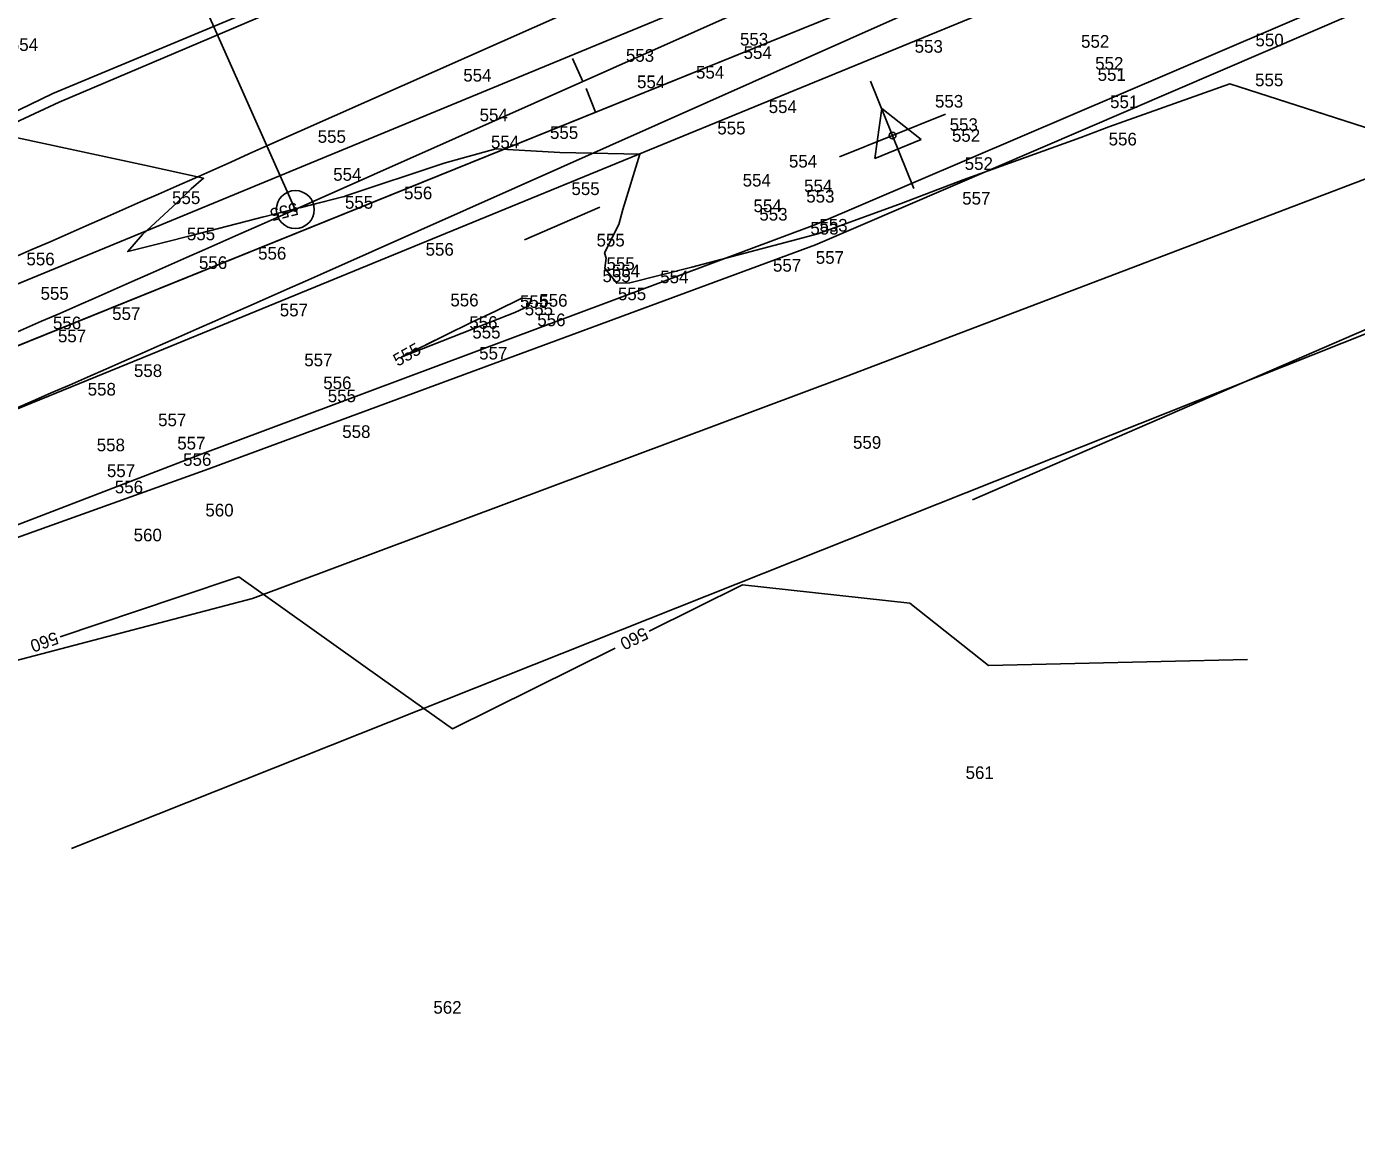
# Model space of a CAD drawing. Extents: x 1787461 to 1970323, y 938412 to 1118748.
# Drawn here: x 1966957.7 to 1967168, y 1117405.8 to 1117583.4 of the extents above; entities that cross this region are included whole.
import ezdxf

# ---------------------------------------------------------------- set-up
doc = ezdxf.new("R2010")
doc.units = 0
for name, color, linetype in [('Default', 7, 'Continuous'), ('HHA ADDITIONAL XSs', 7, 'Continuous'), ('Level 1', 7, 'Continuous'), ('RD_EX_DR_Pipe', 7, 'Continuous'), ('RD_EX_DV_Prop', 7, 'Continuous'), ('RD_EX_Fence_Other', 7, 'Continuous'), ('RD_EX_Road', 7, 'Continuous'), ('RD_EX_VEG', 7, 'Continuous'), ('RD_HC_CL', 7, 'Continuous'), ('RD_HC_CL_Rel', 7, 'Continuous'), ('RD_HC_Data', 7, 'Continuous'), ('RD_HC_Data_Rel', 7, 'Continuous'), ('RD_HC_Data_Tic', 7, 'Continuous'), ('RD_HC_Data_Tic_Rel', 7, 'Continuous'), ('RD_PD_Final_TrvlWay', 7, 'Continuous'), ('RD_SMD_Locator', 7, 'Continuous')]:
    doc.layers.add(name, color=color, linetype=linetype)

msp = doc.modelspace()

# ---------------------------------------------------------------- linework, layer by layer
at = {"layer": 'Default'}
for points in [[(1966956.22, 1117565.78), (1966976.29, 1117561.41), (1966985.65, 1117559.37), (1966983.68, 1117557.71), (1966981.41, 1117555.46), (1966976, 1117550.46), (1966973.66, 1117547.76), (1966979.57, 1117549.27), (1966983.55, 1117550.28), (1966993.93, 1117552.93), (1967007.69, 1117556.42), (1967007.94, 1117556.5), (1967008.17, 1117556.58), (1967023.71, 1117561.74), (1967031.88, 1117564.04), (1967042.04, 1117563.46), (1967054.65, 1117563.2), (1967051.98, 1117554.44), (1967051.36, 1117552.04), (1967049.1, 1117547.57), (1967049.36, 1117546.73), (1967049.11, 1117545.12), (1967051.03, 1117542.76), (1967053.07, 1117542.82), (1967062.9, 1117545.28), (1967078.65, 1117549.48), (1967082.04, 1117550.36), (1967082.81, 1117550.57), (1967096.02, 1117555.37), (1967105.81, 1117559.1), (1967124.45, 1117565.81), (1967128.88, 1117567.48), (1967148, 1117574.3), (1967186.2, 1117562)], [(1967000.95, 1117554.71), (1967007.69, 1117556.42), (1967007.94, 1117556.5), (1967008.17, 1117556.58), (1967023.71, 1117561.74), (1967031.88, 1117564.04), (1967042.04, 1117563.46), (1967054.65, 1117563.2), (1967051.98, 1117554.44), (1967051.36, 1117552.04), (1967049.1, 1117547.57), (1967049.36, 1117546.73), (1967049.11, 1117545.12), (1967051.03, 1117542.76), (1967053.07, 1117542.82), (1967062.9, 1117545.28), (1967078.65, 1117549.48), (1967082.04, 1117550.36), (1967082.81, 1117550.57), (1967096.02, 1117555.37), (1967105.81, 1117559.1), (1967124.45, 1117565.81), (1967128.88, 1117567.48), (1967148, 1117574.3), (1967167.54, 1117568.01)], [(1967000.95, 1117554.71), (1967007.69, 1117556.42), (1967007.94, 1117556.5), (1967008.17, 1117556.58), (1967023.71, 1117561.74), (1967031.88, 1117564.04), (1967042.04, 1117563.46), (1967054.65, 1117563.2), (1967051.98, 1117554.44), (1967051.36, 1117552.04), (1967049.1, 1117547.57), (1967049.36, 1117546.73), (1967049.11, 1117545.12), (1967051.03, 1117542.76), (1967053.07, 1117542.82), (1967062.9, 1117545.28), (1967078.65, 1117549.48), (1967082.04, 1117550.36), (1967082.81, 1117550.57), (1967096.02, 1117555.37), (1967105.81, 1117559.1), (1967124.45, 1117565.81), (1967128.88, 1117567.48), (1967148, 1117574.3), (1967167.54, 1117568.01)], [(1967000.95, 1117554.71), (1967007.69, 1117556.42), (1967007.94, 1117556.5), (1967008.17, 1117556.58), (1967023.71, 1117561.74), (1967031.88, 1117564.04), (1967042.04, 1117563.46), (1967054.65, 1117563.2), (1967051.98, 1117554.44), (1967051.36, 1117552.04), (1967049.1, 1117547.57), (1967049.36, 1117546.73), (1967049.11, 1117545.12), (1967051.03, 1117542.76), (1967053.07, 1117542.82), (1967062.9, 1117545.28), (1967078.65, 1117549.48), (1967082.04, 1117550.36), (1967082.81, 1117550.57), (1967096.02, 1117555.37), (1967105.81, 1117559.1), (1967124.45, 1117565.81), (1967128.88, 1117567.48), (1967148, 1117574.3), (1967167.54, 1117568.01)], [(1967000.95, 1117554.71), (1967007.69, 1117556.42), (1967007.94, 1117556.5), (1967008.17, 1117556.58), (1967023.71, 1117561.74), (1967031.88, 1117564.04), (1967042.04, 1117563.46), (1967054.65, 1117563.2), (1967051.98, 1117554.44), (1967051.36, 1117552.04), (1967049.1, 1117547.57), (1967049.36, 1117546.73), (1967049.11, 1117545.12), (1967051.03, 1117542.76), (1967053.07, 1117542.82), (1967062.9, 1117545.28), (1967078.65, 1117549.48), (1967082.04, 1117550.36), (1967082.81, 1117550.57), (1967096.02, 1117555.37), (1967105.81, 1117559.1), (1967124.45, 1117565.81), (1967128.88, 1117567.48), (1967148, 1117574.3), (1967167.54, 1117568.01)], [(1967000.95, 1117554.71), (1967007.69, 1117556.42), (1967007.94, 1117556.5), (1967008.17, 1117556.58), (1967023.71, 1117561.74), (1967031.88, 1117564.04), (1967042.04, 1117563.46), (1967054.65, 1117563.2), (1967051.98, 1117554.44), (1967051.36, 1117552.04), (1967049.1, 1117547.57), (1967049.36, 1117546.73), (1967049.11, 1117545.12), (1967051.03, 1117542.76), (1967053.07, 1117542.82), (1967062.9, 1117545.28), (1967078.65, 1117549.48), (1967082.04, 1117550.36), (1967082.81, 1117550.57), (1967096.02, 1117555.37), (1967105.81, 1117559.1), (1967124.45, 1117565.81), (1967128.88, 1117567.48), (1967148, 1117574.3), (1967167.54, 1117568.01)], [(1967000.95, 1117554.71), (1967007.69, 1117556.42), (1967007.94, 1117556.5), (1967008.17, 1117556.58), (1967023.71, 1117561.74), (1967031.88, 1117564.04), (1967042.04, 1117563.46), (1967054.65, 1117563.2), (1967051.98, 1117554.44), (1967051.36, 1117552.04), (1967049.1, 1117547.57), (1967049.36, 1117546.73), (1967049.11, 1117545.12), (1967051.03, 1117542.76), (1967053.07, 1117542.82), (1967062.9, 1117545.28), (1967078.65, 1117549.48), (1967082.04, 1117550.36), (1967082.81, 1117550.57), (1967096.02, 1117555.37), (1967105.81, 1117559.1), (1967124.45, 1117565.81), (1967128.88, 1117567.48), (1967148, 1117574.3), (1967167.54, 1117568.01)], [(1966827.07, 1117562.81), (1966852.87, 1117556.35), (1966869.59, 1117558.18), (1966944.3, 1117568.38), (1966948.44, 1117567.48), (1966956.22, 1117565.78), (1966976.29, 1117561.41), (1966985.65, 1117559.37), (1966983.68, 1117557.71), (1966981.41, 1117555.46), (1966976, 1117550.46), (1966973.66, 1117547.76), (1966979.57, 1117549.27), (1966983.55, 1117550.28), (1966993.93, 1117552.93), (1966995.13, 1117553.24)], [(1966827.07, 1117562.81), (1966852.87, 1117556.35), (1966869.59, 1117558.18), (1966944.3, 1117568.38), (1966948.44, 1117567.48), (1966956.22, 1117565.78), (1966976.29, 1117561.41), (1966985.65, 1117559.37), (1966983.68, 1117557.71), (1966981.41, 1117555.46), (1966976, 1117550.46), (1966973.66, 1117547.76), (1966979.57, 1117549.27), (1966983.55, 1117550.28), (1966993.93, 1117552.93), (1966995.13, 1117553.24)], [(1966827.07, 1117562.81), (1966852.87, 1117556.35), (1966869.59, 1117558.18), (1966944.3, 1117568.38), (1966948.44, 1117567.48), (1966956.22, 1117565.78), (1966976.29, 1117561.41), (1966985.65, 1117559.37), (1966983.68, 1117557.71), (1966981.41, 1117555.46), (1966976, 1117550.46), (1966973.66, 1117547.76), (1966979.57, 1117549.27), (1966983.55, 1117550.28), (1966993.93, 1117552.93), (1966995.13, 1117553.24)], [(1966827.07, 1117562.81), (1966852.87, 1117556.35), (1966869.59, 1117558.18), (1966944.3, 1117568.38), (1966948.44, 1117567.48), (1966956.22, 1117565.78), (1966976.29, 1117561.41), (1966985.65, 1117559.37), (1966983.68, 1117557.71), (1966981.41, 1117555.46), (1966976, 1117550.46), (1966973.66, 1117547.76), (1966979.57, 1117549.27), (1966983.55, 1117550.28), (1966993.93, 1117552.93), (1966995.13, 1117553.24)], [(1966827.07, 1117562.81), (1966852.87, 1117556.35), (1966869.59, 1117558.18), (1966944.3, 1117568.38), (1966948.44, 1117567.48), (1966956.22, 1117565.78), (1966976.29, 1117561.41), (1966985.65, 1117559.37), (1966983.68, 1117557.71), (1966981.41, 1117555.46), (1966976, 1117550.46), (1966973.66, 1117547.76), (1966979.57, 1117549.27), (1966983.55, 1117550.28), (1966993.93, 1117552.93), (1966995.13, 1117553.24)], [(1966827.07, 1117562.81), (1966852.87, 1117556.35), (1966869.59, 1117558.18), (1966944.3, 1117568.38), (1966948.44, 1117567.48), (1966956.22, 1117565.78), (1966976.29, 1117561.41), (1966985.65, 1117559.37), (1966983.68, 1117557.71), (1966981.41, 1117555.46), (1966976, 1117550.46), (1966973.66, 1117547.76), (1966979.57, 1117549.27), (1966983.55, 1117550.28), (1966993.93, 1117552.93), (1966995.13, 1117553.24)], [(1967036.01, 1117540.41), (1967037.52, 1117540.3), (1967037.07, 1117539.15), (1967034.87, 1117538.13), (1967028.32, 1117535.55), (1967016.9, 1117531.06), (1967023.9, 1117534.57), (1967028.01, 1117536.54), (1967031.83, 1117538.37), (1967036.01, 1117540.41)], [(1967036.01, 1117540.41), (1967037.52, 1117540.3), (1967037.07, 1117539.15), (1967034.87, 1117538.13), (1967028.32, 1117535.55), (1967018.39, 1117531.65)], [(1967036.01, 1117540.41), (1967037.52, 1117540.3), (1967037.07, 1117539.15), (1967034.87, 1117538.13), (1967028.32, 1117535.55), (1967018.39, 1117531.65)], [(1967036.01, 1117540.41), (1967037.52, 1117540.3), (1967037.07, 1117539.15), (1967034.87, 1117538.13), (1967028.32, 1117535.55), (1967018.39, 1117531.65)], [(1967036.01, 1117540.41), (1967037.52, 1117540.3), (1967037.07, 1117539.15), (1967034.87, 1117538.13), (1967028.32, 1117535.55), (1967018.39, 1117531.65)], [(1967036.01, 1117540.41), (1967037.52, 1117540.3), (1967037.07, 1117539.15), (1967034.87, 1117538.13), (1967028.32, 1117535.55), (1967018.39, 1117531.65)], [(1967036.01, 1117540.41), (1967037.52, 1117540.3), (1967037.07, 1117539.15), (1967034.87, 1117538.13), (1967028.32, 1117535.55), (1967018.39, 1117531.65)], [(1967020.82, 1117533.03), (1967023.9, 1117534.57), (1967028.01, 1117536.54), (1967031.83, 1117538.37), (1967036.01, 1117540.41)], [(1967020.82, 1117533.03), (1967023.9, 1117534.57), (1967028.01, 1117536.54), (1967031.83, 1117538.37), (1967036.01, 1117540.41)], [(1967020.82, 1117533.03), (1967023.9, 1117534.57), (1967028.01, 1117536.54), (1967031.83, 1117538.37), (1967036.01, 1117540.41)], [(1967020.82, 1117533.03), (1967023.9, 1117534.57), (1967028.01, 1117536.54), (1967031.83, 1117538.37), (1967036.01, 1117540.41)], [(1967020.82, 1117533.03), (1967023.9, 1117534.57), (1967028.01, 1117536.54), (1967031.83, 1117538.37), (1967036.01, 1117540.41)], [(1967020.82, 1117533.03), (1967023.9, 1117534.57), (1967028.01, 1117536.54), (1967031.83, 1117538.37), (1967036.01, 1117540.41)], [(1967050.76, 1117485.04), (1967025.02, 1117472.26), (1967013.95, 1117480.14), (1966991.25, 1117496.3), (1966981.5, 1117493.04), (1966962.98, 1117486.85)], [(1967050.76, 1117485.04), (1967025.02, 1117472.26), (1967013.95, 1117480.14), (1966991.25, 1117496.3), (1966981.5, 1117493.04), (1966962.98, 1117486.85)], [(1967050.76, 1117485.04), (1967025.02, 1117472.26), (1967013.95, 1117480.14), (1966991.25, 1117496.3), (1966981.5, 1117493.04), (1966962.98, 1117486.85)], [(1967050.76, 1117485.04), (1967025.02, 1117472.26), (1967013.95, 1117480.14), (1966991.25, 1117496.3), (1966981.5, 1117493.04), (1966962.98, 1117486.85)], [(1967050.76, 1117485.04), (1967025.02, 1117472.26), (1967013.95, 1117480.14), (1966991.25, 1117496.3), (1966981.5, 1117493.04), (1966962.98, 1117486.85)], [(1967050.76, 1117485.04), (1967025.02, 1117472.26), (1967013.95, 1117480.14), (1966991.25, 1117496.3), (1966981.5, 1117493.04), (1966962.98, 1117486.85)], [(1967050.76, 1117485.04), (1967025.02, 1117472.26), (1967013.95, 1117480.14), (1966991.25, 1117496.3), (1966981.5, 1117493.04), (1966962.98, 1117486.85)], [(1967150.81, 1117483.25), (1967109.82, 1117482.32), (1967097.4, 1117492.18), (1967070.91, 1117495.04), (1967056.14, 1117487.71)], [(1967150.81, 1117483.25), (1967109.82, 1117482.32), (1967097.4, 1117492.18), (1967070.91, 1117495.04), (1967056.14, 1117487.71)], [(1967150.81, 1117483.25), (1967109.82, 1117482.32), (1967097.4, 1117492.18), (1967070.91, 1117495.04), (1967056.14, 1117487.71)], [(1967150.81, 1117483.25), (1967109.82, 1117482.32), (1967097.4, 1117492.18), (1967070.91, 1117495.04), (1967056.14, 1117487.71)], [(1967150.81, 1117483.25), (1967109.82, 1117482.32), (1967097.4, 1117492.18), (1967070.91, 1117495.04), (1967056.14, 1117487.71)], [(1967150.81, 1117483.25), (1967109.82, 1117482.32), (1967097.4, 1117492.18), (1967070.91, 1117495.04), (1967056.14, 1117487.71)], [(1967150.81, 1117483.25), (1967109.82, 1117482.32), (1967097.4, 1117492.18), (1967070.91, 1117495.04), (1967056.14, 1117487.71)]]:
    msp.add_lwpolyline(points, dxfattribs=at)
at = {"layer": 'HHA ADDITIONAL XSs'}
msp.add_lwpolyline([(1969308.89, 1117819.66), (1967912.94, 1117853.44), (1967442.55, 1117653.93), (1967107.32, 1117508.48)], dxfattribs=at)
at = {"layer": 'Level 1'}
msp.add_lwpolyline([(1968654.57, 1117840.68), (1968058.24, 1117848.48), (1967686.38, 1117740.3), (1966964.76, 1117453.35)], dxfattribs=at)
at = {"layer": 'RD_EX_DR_Pipe'}
msp.add_line((1967036.42, 1117549.62), (1967048.36, 1117554.77), dxfattribs=at)
at = {"layer": 'RD_EX_DV_Prop'}
msp.add_line((1966769.51, 1117457.48), (1967696.84, 1117832.06), dxfattribs=at)
at = {"layer": 'RD_EX_Fence_Other'}
for points in [[(1966803.22, 1117549.06), (1966808.8, 1117506.9), (1966864.07, 1117525.43), (1966962.8, 1117571.4), (1967060.23, 1117612.78), (1967157.77, 1117654.58), (1967254.5, 1117693.48), (1967317.6, 1117718.63)], [(1966879.09, 1117474.94), (1966985.88, 1117513.17), (1967082.44, 1117548.84), (1967188.89, 1117594.6), (1967260.47, 1117628.39)], [(1966814.04, 1117405.76), (1966802.15, 1117419.77), (1966805.19, 1117443.48), (1966993.4, 1117492.9), (1967087.17, 1117527.94), (1967198.46, 1117570.29), (1967208.88, 1117573.86), (1967251.36, 1117534.17)]]:
    msp.add_lwpolyline(points, dxfattribs=at)
at = {"layer": 'RD_EX_Road'}
for points in [[(1966768.28, 1117466.83), (1966868.93, 1117506.7), (1966969.96, 1117548.31), (1967069.86, 1117589.6), (1967171.37, 1117630.89), (1967269.56, 1117671.02), (1967319.89, 1117691.93), (1967370.29, 1117712.23), (1967469.03, 1117750.91), (1967565.44, 1117788.86), (1967660.02, 1117826.88), (1967693.17, 1117840.55), (1967696.66, 1117832.16)], [(1966774.52, 1117449.93), (1966874.96, 1117489.75), (1966977.23, 1117531.51), (1967077.03, 1117572.42), (1967179.47, 1117614.42), (1967276.75, 1117654.08), (1967307.6, 1117666.03)]]:
    msp.add_lwpolyline(points, dxfattribs=at)
at = {"layer": 'RD_EX_VEG'}
for points in [[(1966803.22, 1117549.06), (1966801.85, 1117502.56), (1966864.07, 1117525.43), (1966961.82, 1117572.79), (1967059.09, 1117613.38), (1967156.27, 1117655.27), (1967254.08, 1117694.01), (1967316.99, 1117719.5)], [(1966832.92, 1117460.39), (1966879.09, 1117474.94), (1966985, 1117515.6), (1967082.35, 1117552.01), (1967187.28, 1117596.9), (1967283.89, 1117634.57), (1967305.16, 1117647.66)]]:
    msp.add_lwpolyline(points, dxfattribs=at)
at = {"layer": 'RD_HC_CL'}
msp.add_line((1966769.51, 1117457.48), (1967848.24, 1117893.22), dxfattribs=at)
at = {"layer": 'RD_HC_CL_Rel'}
msp.add_line((1967000.16, 1117554.42), (1967182.71, 1117635.7), dxfattribs=at)
msp.add_arc((1964669.71, 1122788.65), 5729.58, 291.995896, 294.000153, dxfattribs=at)
at = {"layer": 'RD_HC_Data'}
for p, q in [((1967098.04, 1117557.74), (1967091.18, 1117574.74)), ((1967086.27, 1117562.73), (1967103.04, 1117569.51)), ((1967091.83, 1117562.51), (1967092.94, 1117570.38)), ((1967092.94, 1117570.38), (1967099.19, 1117565.48)), ((1967091.83, 1117562.51), (1967099.19, 1117565.48))]:
    msp.add_line(p, q, dxfattribs=at)
msp.add_circle((1967094.66, 1117566.12), 0.529, dxfattribs=at)
at = {"layer": 'RD_HC_Data_Rel'}
msp.add_line((1967000.16, 1117554.42), (1966940.2, 1117689.08), dxfattribs=at)
for radius in [3, 0.282]:
    msp.add_circle((1967000.16, 1117554.42), radius, dxfattribs=at)
at = {"layer": 'RD_HC_Data_Tic'}
msp.add_line((1967047.67, 1117569.84), (1967046.18, 1117573.55), dxfattribs=at)
at = {"layer": 'RD_HC_Data_Tic_Rel'}
msp.add_line((1967045.64, 1117574.68), (1967044.02, 1117578.33), dxfattribs=at)
at = {"layer": 'RD_PD_Final_TrvlWay'}
for p, q in [((1966995.68, 1117564.47), (1967178.24, 1117645.75)), ((1967004.63, 1117544.37), (1967187.19, 1117625.65))]:
    msp.add_line(p, q, dxfattribs=at)
for radius, start, end in [(5718.58, 291.9959, 294.00015), (5740.58, 291.995896, 294.000153)]:
    msp.add_arc((1964669.71, 1122788.65), radius, start, end, dxfattribs=at)
at = {"layer": 'RD_SMD_Locator'}
msp.add_circle((1967094.66, 1117566.12), 0.001, dxfattribs=at)

# ---------------------------------------------------------------- texts
at = {"layer": 'Default'}
for s, p in [('554', (1966955, 1117579.5)), ('553', (1967070.52, 1117580.35)), ('552', (1967124.48, 1117580.01)), ('550', (1967152.07, 1117580.23)), ('553', (1967052.47, 1117577.79)), ('554', (1967071.09, 1117578.24)), ('553', (1967098.15, 1117579.22)), ('554', (1967063.56, 1117575.12)), ('552', (1967126.71, 1117576.54)), ('554', (1967026.74, 1117574.66)), ('554', (1967054.23, 1117573.62)), ('551', (1967127.1, 1117574.77)), ('555', (1967152.01, 1117573.92)), ('554', (1967075.06, 1117569.68)), ('553', (1967101.37, 1117570.54)), ('551', (1967129.07, 1117570.46)), ('554', (1967029.32, 1117568.38)), ('553', (1967103.69, 1117566.85)), ('555', (1967003.71, 1117564.97)), ('555', (1967040.46, 1117565.58)), ('555', (1967066.93, 1117566.3)), ('552', (1967104.05, 1117565.14)), ('556', (1967128.84, 1117564.56)), ('554', (1967031.12, 1117564.09)), ('554', (1967078.26, 1117561.06)), ('552', (1967106.07, 1117560.69)), ('554', (1967006.16, 1117558.97)), ('555', (1967043.85, 1117556.71)), ('554', (1967070.94, 1117558.06)), ('554', (1967080.66, 1117557.16)), ('555', (1966980.67, 1117555.28)), ('555', (1967008.02, 1117554.55)), ('556', (1967017.37, 1117556.04)), ('553', (1967081, 1117555.52)), ('557', (1967105.67, 1117555.2)), ('554', (1967072.65, 1117554.01)), ('553', (1967073.58, 1117552.67)), ('553', (1967081.65, 1117550.46)), ('553', (1967083.08, 1117550.93)), ('555', (1966983.01, 1117549.56)), ('555', (1967047.82, 1117548.58)), ('556', (1966994.28, 1117546.5)), ('556', (1967020.78, 1117547.12)), ('557', (1967082.51, 1117545.84)), ('556', (1966957.63, 1117545.59)), ('556', (1966984.92, 1117545.02)), ('555', (1967049.4, 1117544.86)), ('554', (1967050.24, 1117543.72)), ('557', (1967075.74, 1117544.59)), ('555', (1967048.76, 1117542.94)), ('554', (1967057.9, 1117542.76)), ('555', (1966959.86, 1117540.15)), ('555', (1967051.21, 1117540.08)), ('557', (1966997.71, 1117537.52)), ('556', (1967024.7, 1117539.1)), ('555', (1967035.72, 1117538.87)), ('555', (1967036.47, 1117537.68)), ('556', (1967038.77, 1117539.05)), ('556', (1966961.82, 1117535.48)), ('557', (1966971.19, 1117536.95)), ('556', (1967027.69, 1117535.55)), ('556', (1967038.45, 1117535.97)), ('557', (1966962.61, 1117533.42)), ('555', (1967028.17, 1117534.02)), ('557', (1967001.58, 1117529.63)), ('557', (1967029.25, 1117530.7)), ('558', (1966974.64, 1117527.93)), ('558', (1966967.32, 1117525)), ('556', (1967004.59, 1117526.01)), ('555', (1967005.3, 1117523.95)), ('557', (1966978.46, 1117520.15)), ('558', (1967007.59, 1117518.29)), ('558', (1966968.75, 1117516.18)), ('557', (1966981.49, 1117516.47)), ('559', (1967088.4, 1117516.58)), ('557', (1966970.36, 1117512.1)), ('556', (1966982.42, 1117513.88)), ('556', (1966971.61, 1117509.53)), ('560', (1966985.94, 1117505.88)), ('560', (1966974.59, 1117501.94)), ('561', (1967106.21, 1117464.35)), ('562', (1967022.01, 1117427.23))]:
    msp.add_text(s, height=2, dxfattribs=at).set_placement(p)
for s, rotation, p in [('555', 194.2013, (1967000.32, 1117555.58)), ('555', 194.2013, (1967000.32, 1117555.58)), ('555', 194.2013, (1967000.32, 1117555.58)), ('555', 194.2013, (1967000.32, 1117555.58)), ('555', 194.2013, (1967000.32, 1117555.58)), ('555', 194.2013, (1967000.32, 1117555.58)), ('555', 29.6014, (1967016.37, 1117529.53)), ('555', 29.6014, (1967016.37, 1117529.53)), ('555', 29.6014, (1967016.37, 1117529.53)), ('555', 29.6014, (1967016.37, 1117529.53)), ('555', 29.6014, (1967016.37, 1117529.53)), ('555', 29.6014, (1967016.37, 1117529.53)), ('560', 199.2198, (1966962.25, 1117487.68)), ('560', 199.2198, (1966962.25, 1117487.68)), ('560', 199.2198, (1966962.25, 1117487.68)), ('560', 199.2198, (1966962.25, 1117487.68)), ('560', 199.2198, (1966962.25, 1117487.68)), ('560', 199.2198, (1966962.25, 1117487.68)), ('560', 199.2198, (1966962.25, 1117487.68)), ('560', 206.4014, (1967055.33, 1117488.42)), ('560', 206.4014, (1967055.33, 1117488.42)), ('560', 206.4014, (1967055.33, 1117488.42)), ('560', 206.4014, (1967055.33, 1117488.42)), ('560', 206.4014, (1967055.33, 1117488.42)), ('560', 206.4014, (1967055.33, 1117488.42)), ('560', 206.4014, (1967055.33, 1117488.42))]:
    msp.add_text(s, height=2, rotation=rotation, dxfattribs=at).set_placement(p)

doc.saveas('drawing.dxf')
